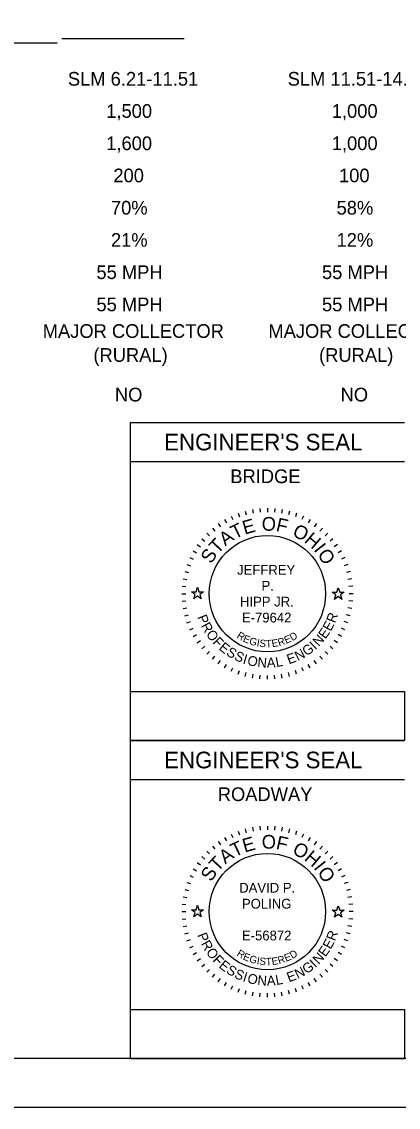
# Model space of a CAD drawing. Extents: x 0 to 34, y 0 to 22.
# Drawn here: x 7.34 to 11.19, y 0 to 11.1 of the extents above; entities that cross this region are included whole.
import ezdxf

# ---------------------------------------------------------------- set-up
doc = ezdxf.new("R2010")
doc.units = 0
for name, color, linetype in [('SH_Border', 7, 'Continuous'), ('SH_Cut_Line', 7, 'Continuous'), ('SH_Data', 7, 'Continuous'), ('SH_Text', 7, 'Continuous')]:
    doc.layers.add(name, color=color, linetype=linetype)

msp = doc.modelspace()

# ---------------------------------------------------------------- linework, layer by layer
at = {"layer": 'SH_Border'}
msp.add_lwpolyline([(1.5, 21.5), (33.5, 21.5), (33.5, 0.5), (1.5, 0.5)], close=True, dxfattribs=at)
at = {"layer": 'SH_Cut_Line'}
msp.add_lwpolyline([(0, 0), (34, 0), (34, 22), (0, 22)], close=True, dxfattribs=at)
at = {"layer": 'SH_Data'}
for p, q in [((7.7, 10.877), (3.566, 10.877)), ((9, 10.922), (7.75, 10.922)), ((8.45, 3.75), (8.45, 7)), ((8.45, 7), (11.25, 7)), ((8.45, 6.6), (11.25, 6.6)), ((9.698, 6.112), (9.705, 6.072)), ((9.774, 6.122), (9.777, 6.082)), ((9.85, 6.125), (9.85, 6.085)), ((9.926, 6.122), (9.923, 6.082)), ((10.002, 6.112), (9.995, 6.072)), ((9.413, 6.008), (9.433, 5.973)), ((9.48, 6.043), (9.497, 6.007)), ((9.551, 6.072), (9.564, 6.035)), ((9.624, 6.095), (9.634, 6.057)), ((10.076, 6.095), (10.066, 6.057)), ((10.149, 6.072), (10.136, 6.035)), ((10.22, 6.043), (10.203, 6.007)), ((10.287, 6.008), (10.267, 5.973)), ((9.288, 5.92), (9.313, 5.89)), ((9.348, 5.967), (9.371, 5.934)), ((10.352, 5.967), (10.329, 5.934)), ((10.412, 5.92), (10.387, 5.89)), ((9.18, 5.812), (9.21, 5.787)), ((9.231, 5.869), (9.26, 5.84)), ((10.469, 5.869), (10.44, 5.84)), ((10.52, 5.812), (10.49, 5.787)), ((9.092, 5.688), (9.127, 5.668)), ((9.133, 5.752), (9.166, 5.729)), ((10.567, 5.752), (10.534, 5.729)), ((10.608, 5.688), (10.573, 5.668)), ((9.028, 5.549), (9.065, 5.536)), ((9.057, 5.62), (9.093, 5.603)), ((10.643, 5.62), (10.607, 5.603)), ((10.672, 5.549), (10.635, 5.536)), ((9.005, 5.476), (9.043, 5.466)), ((10.695, 5.476), (10.657, 5.466)), ((8.988, 5.402), (9.028, 5.395)), ((10.712, 5.402), (10.672, 5.395)), ((8.975, 5.25), (9.015, 5.25)), ((8.978, 5.326), (9.018, 5.323)), ((10.722, 5.326), (10.682, 5.323)), ((10.725, 5.25), (10.685, 5.25)), ((8.978, 5.174), (9.018, 5.177)), ((8.988, 5.098), (9.028, 5.105)), ((10.712, 5.098), (10.672, 5.105)), ((10.722, 5.174), (10.682, 5.177)), ((9.005, 5.024), (9.043, 5.034)), ((10.695, 5.024), (10.657, 5.034)), ((9.028, 4.951), (9.065, 4.964)), ((9.057, 4.88), (9.093, 4.897)), ((10.643, 4.88), (10.607, 4.897)), ((10.672, 4.951), (10.635, 4.964)), ((9.092, 4.813), (9.127, 4.833)), ((10.608, 4.813), (10.573, 4.833)), ((9.133, 4.748), (9.166, 4.771)), ((9.18, 4.688), (9.21, 4.713)), ((10.52, 4.688), (10.49, 4.713)), ((10.567, 4.748), (10.534, 4.771)), ((9.231, 4.631), (9.26, 4.66)), ((9.288, 4.58), (9.313, 4.61)), ((9.348, 4.533), (9.371, 4.566)), ((10.352, 4.533), (10.329, 4.566)), ((10.412, 4.58), (10.387, 4.61)), ((10.469, 4.631), (10.44, 4.66)), ((9.413, 4.492), (9.433, 4.527)), ((9.48, 4.457), (9.497, 4.493)), ((9.551, 4.428), (9.564, 4.465)), ((9.624, 4.405), (9.634, 4.443)), ((10.076, 4.405), (10.066, 4.443)), ((10.149, 4.428), (10.136, 4.465)), ((10.22, 4.457), (10.203, 4.493)), ((10.287, 4.492), (10.267, 4.527)), ((9.698, 4.388), (9.705, 4.428)), ((9.774, 4.378), (9.777, 4.418)), ((9.85, 4.375), (9.85, 4.415)), ((9.926, 4.378), (9.923, 4.418)), ((10.002, 4.388), (9.995, 4.428)), ((8.45, 3.75), (11.25, 3.75)), ((8.45, 3.75), (11.25, 3.75)), ((8.45, 0.5), (8.45, 3.75)), ((8.45, 3.75), (11.25, 3.75)), ((8.45, 3.35), (11.25, 3.35)), ((9.48, 2.793), (9.497, 2.757)), ((9.551, 2.822), (9.564, 2.785)), ((9.624, 2.845), (9.634, 2.807)), ((9.698, 2.862), (9.705, 2.822)), ((9.774, 2.872), (9.777, 2.832)), ((9.85, 2.875), (9.85, 2.835)), ((9.926, 2.872), (9.923, 2.832)), ((10.002, 2.862), (9.995, 2.822)), ((10.076, 2.845), (10.066, 2.807)), ((10.149, 2.822), (10.136, 2.785)), ((10.22, 2.793), (10.203, 2.757)), ((9.288, 2.67), (9.313, 2.64)), ((9.348, 2.717), (9.371, 2.684)), ((9.413, 2.758), (9.433, 2.723)), ((10.287, 2.758), (10.267, 2.723)), ((10.352, 2.717), (10.329, 2.684)), ((10.412, 2.67), (10.387, 2.64)), ((9.18, 2.562), (9.21, 2.537)), ((9.231, 2.619), (9.26, 2.59)), ((10.469, 2.619), (10.44, 2.59)), ((10.52, 2.562), (10.49, 2.537)), ((9.133, 2.502), (9.166, 2.479)), ((10.567, 2.502), (10.534, 2.479)), ((9.057, 2.37), (9.093, 2.353)), ((9.092, 2.438), (9.127, 2.418)), ((10.608, 2.438), (10.573, 2.418)), ((10.643, 2.37), (10.607, 2.353)), ((9.005, 2.226), (9.043, 2.216)), ((9.028, 2.299), (9.065, 2.286)), ((10.672, 2.299), (10.635, 2.286)), ((10.695, 2.226), (10.657, 2.216)), ((8.988, 2.152), (9.028, 2.145)), ((10.712, 2.152), (10.672, 2.145)), ((8.975, 2), (9.015, 2)), ((8.978, 2.076), (9.018, 2.073)), ((10.722, 2.076), (10.682, 2.073)), ((10.725, 2), (10.685, 2)), ((8.978, 1.924), (9.018, 1.927)), ((10.722, 1.924), (10.682, 1.927)), ((8.988, 1.848), (9.028, 1.855)), ((9.005, 1.774), (9.043, 1.784)), ((10.695, 1.774), (10.657, 1.784)), ((10.712, 1.848), (10.672, 1.855)), ((9.028, 1.701), (9.065, 1.714)), ((10.672, 1.701), (10.635, 1.714)), ((9.057, 1.63), (9.093, 1.647)), ((9.092, 1.563), (9.127, 1.583)), ((10.608, 1.563), (10.573, 1.583)), ((10.643, 1.63), (10.607, 1.647)), ((9.133, 1.498), (9.166, 1.521)), ((9.18, 1.438), (9.21, 1.463)), ((10.52, 1.438), (10.49, 1.463)), ((10.567, 1.498), (10.534, 1.521)), ((9.231, 1.381), (9.26, 1.41)), ((9.288, 1.33), (9.313, 1.36)), ((10.412, 1.33), (10.387, 1.36)), ((10.469, 1.381), (10.44, 1.41)), ((9.348, 1.283), (9.371, 1.316)), ((9.413, 1.242), (9.433, 1.277)), ((9.48, 1.207), (9.497, 1.243)), ((10.22, 1.207), (10.203, 1.243)), ((10.287, 1.242), (10.267, 1.277)), ((10.352, 1.283), (10.329, 1.316)), ((9.551, 1.178), (9.564, 1.215)), ((9.624, 1.155), (9.634, 1.193)), ((9.698, 1.138), (9.705, 1.178)), ((9.774, 1.128), (9.777, 1.168)), ((9.85, 1.125), (9.85, 1.165)), ((9.926, 1.128), (9.923, 1.168)), ((10.002, 1.138), (9.995, 1.178)), ((10.076, 1.155), (10.066, 1.193)), ((10.149, 1.178), (10.136, 1.215)), ((8.45, 0.5), (11.25, 0.5)), ((8.45, 0.5), (11.25, 0.5))]:
    msp.add_line(p, q, dxfattribs=at)
for points in [[(9.074, 5.27), (9.121, 5.27), (9.135, 5.315), (9.149, 5.27), (9.196, 5.27), (9.158, 5.242), (9.173, 5.198), (9.135, 5.225), (9.097, 5.198), (9.112, 5.242)], [(10.513, 5.265), (10.56, 5.265), (10.574, 5.309), (10.589, 5.265), (10.635, 5.265), (10.598, 5.237), (10.612, 5.192), (10.574, 5.22), (10.536, 5.192), (10.551, 5.237)], [(8.45, 3.75), (8.45, 4.25), (11.25, 4.25), (11.25, 3.75)], [(9.074, 2.02), (9.121, 2.02), (9.135, 2.065), (9.149, 2.02), (9.196, 2.02), (9.158, 1.992), (9.173, 1.948), (9.135, 1.975), (9.097, 1.948), (9.112, 1.992)], [(10.513, 2.015), (10.56, 2.015), (10.574, 2.059), (10.589, 2.015), (10.635, 2.015), (10.598, 1.987), (10.612, 1.942), (10.574, 1.97), (10.536, 1.942), (10.551, 1.987)], [(8.45, 0.5), (8.45, 1), (11.25, 1), (11.25, 0.5)]]:
    msp.add_lwpolyline(points, close=True, dxfattribs=at)
for centre in [(9.85, 5.25), (9.85, 2)]:
    msp.add_circle(centre, 0.595, dxfattribs=at)

# ---------------------------------------------------------------- texts
for s, height, p in [("ENGINEER'S SEAL", 0.17, (8.795, 6.715)), ('BRIDGE', 0.14, (9.471, 6.38)), ('JEFFREY', 0.1, (9.54, 5.444)), ('P.', 0.1, (9.79, 5.281)), ('HIPP JR.', 0.1, (9.57, 5.119)), ('E-79642', 0.1, (9.59, 4.956)), ("ENGINEER'S SEAL", 0.17, (8.795, 3.465)), ('ROADWAY', 0.14, (9.343, 3.13)), ('DAVID P.', 0.1, (9.562, 2.194)), ('POLING', 0.1, (9.59, 2.031)), ('E-56872', 0.1, (9.59, 1.706))]:
    msp.add_text(s, height=height, dxfattribs=at).set_placement(p)
for s, height, rotation, p in [('E', 0.14, 15.7571, (9.617, 5.853)), ('O', 0.14, 359.7812, (9.792, 5.894)), ('F', 0.14, 347.4362, (9.931, 5.892)), ('A', 0.14, 36.4747, (9.419, 5.732)), ('T', 0.14, 25.7167, (9.516, 5.804)), ('O', 0.14, 332.2586, (10.096, 5.848)), ('T', 0.14, 46.4344, (9.342, 5.65)), ('H', 0.14, 319.9136, (10.218, 5.782)), ('I', 0.14, 308.367, (10.317, 5.697)), ('S', 0.14, 57.1924, (9.276, 5.548)), ('O', 0.14, 303.1491, (10.356, 5.653)), ('P', 0.1, 291.494, (9.132, 5.012)), ('R', 0.1, 69.2322, (10.541, 4.944)), ('R', 0.1, 298.7311, (9.168, 4.923)), ('E', 0.1, 54.758, (10.443, 4.781)), ('E', 0.1, 61.9951, (10.497, 4.859)), ('O', 0.1, 306.4666, (9.218, 4.835)), ('F', 0.1, 314.7068, (9.284, 4.748)), ('R', 0.075, 327.8239, (9.53, 4.804)), ('E', 0.075, 337.7777, (9.594, 4.763)), ('G', 0.075, 344.2727, (9.658, 4.735)), ('I', 0.075, 350.6464, (9.737, 4.713)), ('S', 0.075, 353.7858, (9.765, 4.708)), ('T', 0.075, 3.0061, (9.835, 4.701)), ('E', 0.075, 8.9826, (9.899, 4.703)), ('R', 0.075, 17.6836, (9.969, 4.713)), ('E', 0.075, 23.3052, (10.041, 4.736)), ('D', 0.075, 31.466, (10.105, 4.764)), ('N', 0.1, 47.0224, (10.374, 4.705)), ('E', 0.1, 321.4393, (9.347, 4.685)), ('S', 0.1, 328.6764, (9.422, 4.627)), ('N', 0.1, 27.3113, (10.16, 4.56)), ('G', 0.1, 35.0469, (10.25, 4.608)), ('I', 0.1, 43.287, (10.338, 4.672)), ('S', 0.1, 335.9134, (9.504, 4.578)), ('I', 0.1, 343.1505, (9.592, 4.539)), ('O', 0.1, 346.8859, (9.638, 4.524)), ('N', 0.1, 355.1261, (9.745, 4.501)), ('A', 0.1, 2.8617, (9.846, 4.494)), ('L', 0.1, 10.0987, (9.942, 4.499)), ('E', 0.1, 20.0742, (10.07, 4.527)), ('O', 0.14, 359.7812, (9.792, 2.644)), ('F', 0.14, 347.4362, (9.931, 2.642)), ('T', 0.14, 25.7167, (9.516, 2.554)), ('E', 0.14, 15.7571, (9.617, 2.603)), ('O', 0.14, 332.2586, (10.096, 2.598)), ('T', 0.14, 46.4344, (9.342, 2.4)), ('A', 0.14, 36.4747, (9.419, 2.482)), ('H', 0.14, 319.9136, (10.218, 2.532)), ('S', 0.14, 57.1924, (9.276, 2.298)), ('I', 0.14, 308.367, (10.317, 2.447)), ('O', 0.14, 303.1491, (10.356, 2.403)), ('P', 0.1, 291.494, (9.132, 1.762)), ('R', 0.1, 69.2322, (10.541, 1.694)), ('R', 0.1, 298.7311, (9.168, 1.673)), ('E', 0.1, 61.9951, (10.497, 1.609)), ('O', 0.1, 306.4666, (9.218, 1.585)), ('F', 0.1, 314.7068, (9.284, 1.498)), ('R', 0.075, 327.8239, (9.53, 1.554)), ('E', 0.075, 337.7777, (9.594, 1.513)), ('E', 0.075, 23.3052, (10.041, 1.486)), ('D', 0.075, 31.466, (10.105, 1.514)), ('N', 0.1, 47.0224, (10.374, 1.455)), ('E', 0.1, 54.758, (10.443, 1.531)), ('E', 0.1, 321.4393, (9.347, 1.435)), ('S', 0.1, 328.6764, (9.422, 1.377)), ('G', 0.075, 344.2727, (9.658, 1.485)), ('I', 0.075, 350.6464, (9.737, 1.463)), ('S', 0.075, 353.7858, (9.765, 1.458)), ('T', 0.075, 3.0061, (9.835, 1.451)), ('E', 0.075, 8.9826, (9.899, 1.453)), ('R', 0.075, 17.6836, (9.969, 1.463)), ('G', 0.1, 35.0469, (10.25, 1.358)), ('I', 0.1, 43.287, (10.338, 1.422)), ('S', 0.1, 335.9134, (9.504, 1.328)), ('I', 0.1, 343.1505, (9.592, 1.289)), ('O', 0.1, 346.8859, (9.638, 1.274)), ('N', 0.1, 355.1261, (9.745, 1.251)), ('A', 0.1, 2.8617, (9.846, 1.244)), ('L', 0.1, 10.0987, (9.942, 1.249)), ('E', 0.1, 20.0742, (10.07, 1.277)), ('N', 0.1, 27.3113, (10.16, 1.31))]:
    msp.add_text(s, height=height, rotation=rotation, dxfattribs=at).set_placement(p)
at = {"layer": 'SH_Text'}
for s, p in [('SLM 6.21-11.51', (7.811, 10.443)), ('SLM 11.51-14.27', (10.057, 10.443)), ('1,500', (8.203, 10.114)), ('1,000', (10.508, 10.114)), ('1,600', (8.203, 9.784)), ('1,000', (10.508, 9.784)), ('200', (8.276, 9.455)), ('100', (10.582, 9.455)), ('70%', (8.251, 9.125)), ('58%', (10.557, 9.125)), ('21%', (8.251, 8.796)), ('12%', (10.557, 8.796)), ('55 MPH', (8.103, 8.466)), ('55 MPH', (10.408, 8.466)), ('55 MPH', (8.103, 8.137)), ('55 MPH', (10.408, 8.137)), ('MAJOR COLLECTOR ', (7.554, 7.865)), ('MAJOR COLLECTOR ', (9.86, 7.865)), ('(RURAL)', (8.072, 7.62)), ('(RURAL)', (10.378, 7.62)), ('NO', (8.292, 7.215)), ('NO', (10.598, 7.215))]:
    msp.add_text(s, height=0.14, dxfattribs=at).set_placement(p)

doc.saveas('drawing.dxf')
